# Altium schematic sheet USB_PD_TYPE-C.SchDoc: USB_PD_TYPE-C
size A4; Date: Not used; ApprovedBy: Not used; CheckedBy: Not used; Author: Not used; CompanyName: STMicroelectronics; DrawnBy: Not used; Engineer: Not used; Organization: Not used; Address1: Not used; Address2: Not used; Address3: Not used; Address4: Not used; DocumentNumber: Not used; Revision: Not used; SheetNumber: 5; SheetTotal: 12
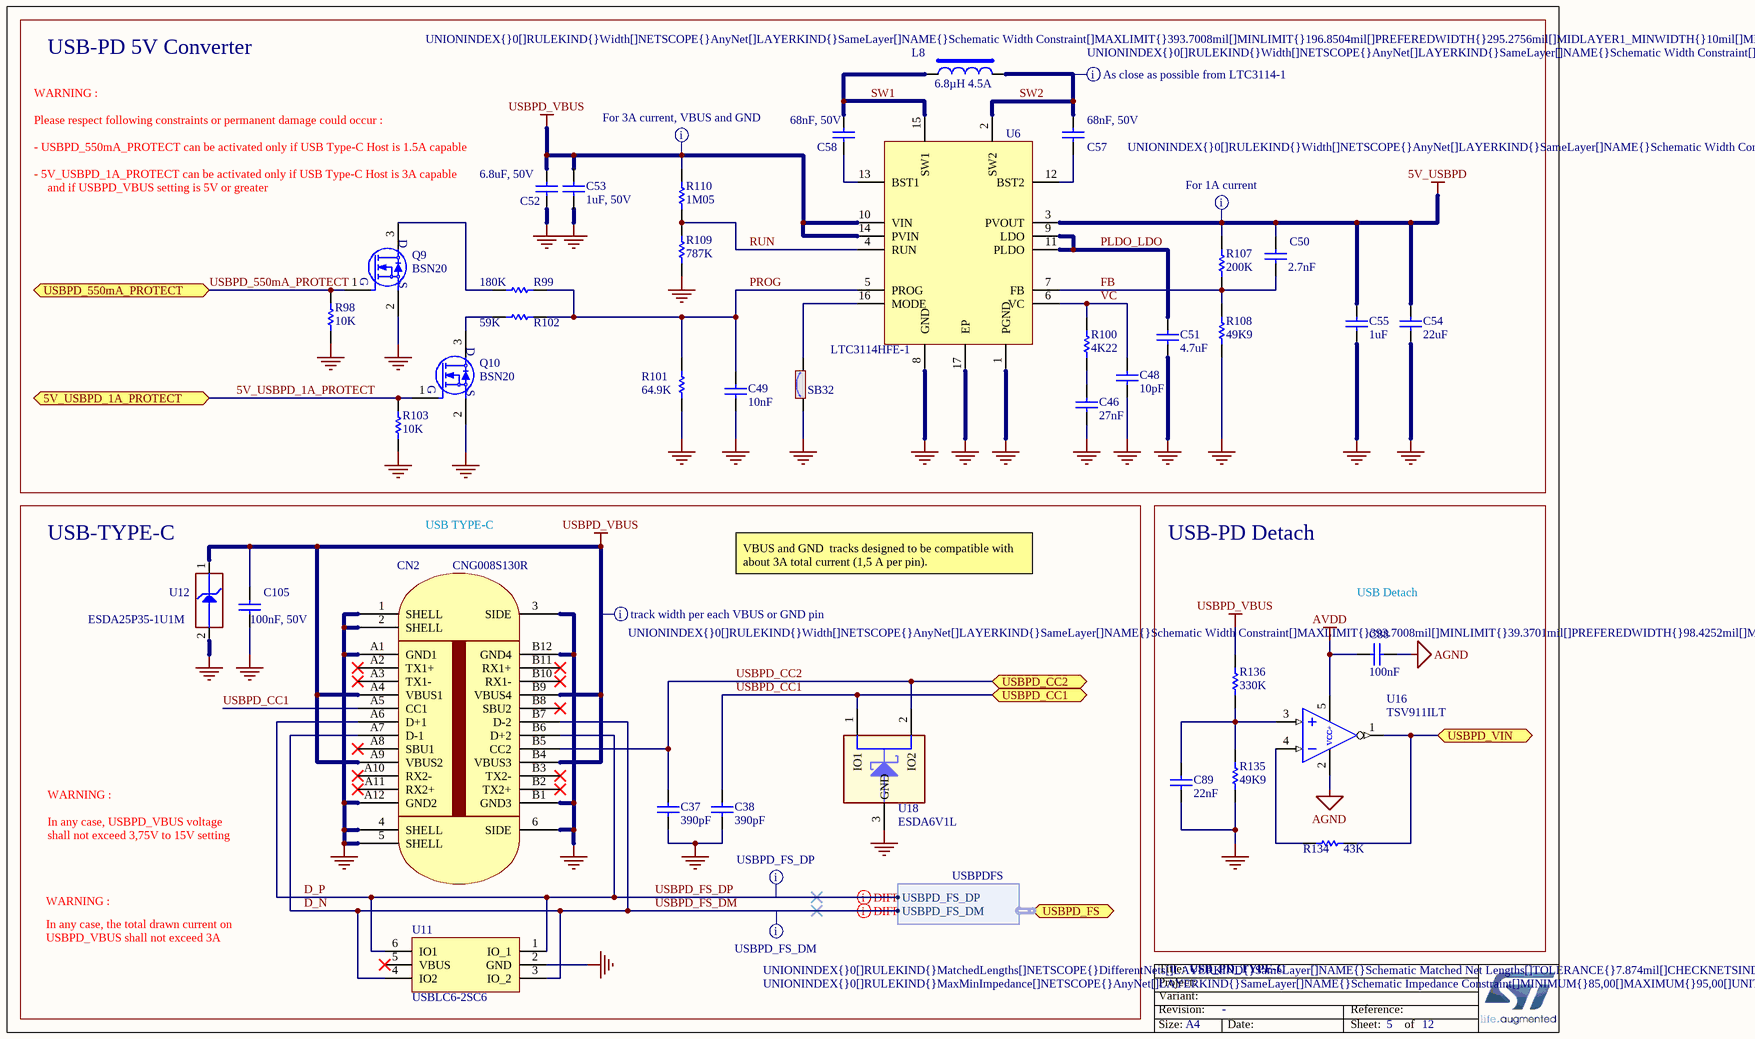
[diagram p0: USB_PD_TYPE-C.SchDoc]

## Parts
C37  value 390pF  [C0402]
C38  value 390pF  [C0402]
C46  value 27nF  [C0805_KEMET_IPC-7351_DENSITY-LEVEL-B_H1P10]  (hidden comment: Capacitor)
C48  value 10pF  [C0603]
C49  value 10nF  [C0603]
C50  value 2.7nF  [C0603_H0P8]  (hidden comment: Capacitor)
C51  value 4.7uF  [C0603]
C52  value 6.8uF, 50V  [C1206_H1P6]
C53  value 1uF, 50V  [C0603_H0P8]  (hidden comment: Capacitor)
C54  value 22uF  [C1210]
C55  value 1uF  [C0603]
C57  value 68nF, 50V  [C0603_H0P8]
C58  value 68nF, 50V  [C0603_H0P8]
C88  value 100nF  [C0402]
C89  value 22nF  [C1206_H0P85]
C105  value 100nF, 50V  [C0603]  (hidden comment: Capacitor)
CN2  value CNG008S130R  [CON_USB-TYPEC_LITKCONN-TECHNOLOGY_CNG008S130R]
L8  value 6.8µH 4.5A  [IND_8040_WURTH_74437358068]
Q9  value BSN20  [MOS_SOT23]
Q10  value BSN20  [MOS_SOT23]
R98  value 10K  [R0603]
R99  value 180K  [R0603]  (hidden comment: Resistor)
R100  value 4K22  [R0603_H0P45]
R101  value 64.9K  [R0603_H0P45]  (hidden comment: Resistor)
R102  value 59K  [R0603_H0P45]  (hidden comment: Resistor)
R103  value 10K  [R0603]
R107  value 200K  [R0603]  (hidden comment: Resistor)
R108  value 49K9  [R0603]  (hidden comment: Resistor)
R109  value 787K  [R0603_H0P45]
R110  value 1M05  [R0603_H0P45]
R134  value 43K  [R0603]
R135  value 49K9  [R0603]
R136  value 330K  [R0603]
SB32  (no value)  [SOLDER-BRIDGE_R0603-0R]
U6  value LTC3114HFE-1  [ICC_TSOP65P640X110_HS-17N]
U11  value USBLC6-2SC6  [ESD_SOT23-6L]
U12  value ESDA25P35-1U1M  [ESD_QFN1610_2N_1K_2A]
U16  value TSV911ILT  [AOP_SOT23-5L_H1P45]
U18  value ESDA6V1L  [ESD_SOT23]

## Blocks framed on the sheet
USB-PD 5V Converter: C46 C48-C55 C57 C58 L8 Q9 Q10 R98-R103 R107-R110 SB32 U6
USB-TYPE-C: C37 C38 C105 CN2 U11 U12 U18
USB-PD Detach: C88 C89 R134-R136 U16

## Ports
5V_USBPD_1A_PROTECT, USBPD_550mA_PROTECT, USBPD_CC1, USBPD_CC2, USBPD_FS (harness USBPDFS), USBPD_VIN

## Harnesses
USBPDFS: USBPD_FS_DM, USBPD_FS_DP

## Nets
5V_USBPD: C50.2 C54.2 C55.2 R107.2 U6.3(PVOUT)
AGND: C88.1 U16.2(VCC-)
AVDD: C88.2 U16.5(VCC+)
GND: C37.1 C38.1 C46.1 C48.1 C49.1 C51.2 C52.1 C53.1 C54.1 C55.1 C89.1 C105.1 CN2.1(SHELL) CN2.2(SHELL) CN2.3(SIDE) CN2.4(SHELL) CN2.5(SHELL) CN2.6(SIDE) CN2.A1(GND1) CN2.A12(GND2) CN2.B1(GND3) CN2.B12(GND4) Q9.2(S) Q10.2(S) R98.1 R101.1 R103.1 R108.1 R109.1 R135.1 SB32.1 U6.1(PGND) U6.8(GND) U6.17(EP) U11.2(GND) U12.2(GND) U18.3(GND)
USBPD_VBUS: C52.2 C53.2 C105.2 CN2.A4(VBUS1) CN2.A9(VBUS2) CN2.B4(VBUS3) CN2.B9(VBUS4) R110.2 R136.2 U6.10(VIN) U6.14(PVIN) U12.1(IO1)
5V_USBPD_1A_PROTECT: Q10.1(G) R103.2 ; port 5V_USBPD_1A_PROTECT
D_N: CN2.A7(D-1) CN2.B7(D-2) U11.3(IO_2) U11.4(IO2) ; port USBPD_FS.USBPD_FS_DM  [also labelled USBPD_FS_DM]
D_P: CN2.A6(D+1) CN2.B6(D+2) U11.1(IO_1) U11.6(IO1) ; port USBPD_FS.USBPD_FS_DP  [also labelled USBPD_FS_DP]
FB: C50.1 R107.1 R108.2 U6.7(FB)
PLDO_LDO: C51.1 U6.9(LDO) U6.11(PLDO)
PROG: C49.2 R99.2 R101.2 R102.2 U6.5(PROG)
RUN: R109.2 R110.1 U6.4(RUN)
SW1: C58.2 L8.1 U6.15(SW1)
SW2: C57.2 L8.2 U6.2(SW2)
USBPD_550mA_PROTECT: Q9.1(G) R98.2 ; port USBPD_550mA_PROTECT
USBPD_CC1: C38.2 CN2.A5(CC1) U18.1(IO1) ; port USBPD_CC1
USBPD_CC2: C37.2 CN2.B5(CC2) U18.2(IO2) ; port USBPD_CC2
USBPD_VIN: R134.2 U16.1(NC) ; port USBPD_VIN
VC: C48.2 R100.2 U6.6(VC)
NetC46_2: C46.2 R100.1
NetC57_1: C57.1 U6.12(BST2)
NetC58_1: C58.1 U6.13(BST1)
NetC89_2: C89.2 R135.2 R136.1 U16.3(IN+)
NetQ9_3: Q9.3(D) R99.1
NetQ10_3: Q10.3(D) R102.1
NetR134_1: R134.1 U16.4(IN-)
NetSB32_2: SB32.2 U6.16(MODE)

Not connected (* = marked no-connect by the designer): CN2 A2(TX1+)* A3(TX1-)* A8(SBU1)* A10(RX2-)* A11(RX2+)* B2(TX2+)* B3(TX2-)* B8(SBU2)* B10(RX1-)* B11(RX1+)*; U11 5(VBUS)*

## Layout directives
differential pair; rule Impedance Constraint [Min = 85.00    Max = 95.00    ]: D_N, D_P
rule Undefined; rule Matched Net Lengths [Tolerance = 0.2mm]; rule Impedance Constraint [Min = 85.00    Max = 95.00    ]: D_N, D_P
rule Width Constraint [Pref Width = 2.5mm    Min Width = 1mm    Max Width = 10mm]: USBPD_VBUS
rule Width Constraint [Pref Width = 5mm    Min Width = 5mm    Max Width = 10mm]: 5V_USBPD, SW2
rule Width Constraint [Pref Width = 7.5mm    Min Width = 5mm    Max Width = 10mm]: USBPD_VBUS

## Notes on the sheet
- WARNING :
- - USBPD_550mA_PROTECT can be activated only if USB Type-C Host is 1.5A capable
- - 5V_USBPD_1A_PROTECT can be activated only if USB Type-C Host is 3A capable
- Please respect following constraints or permanent damage could occur :
- and if USBPD_VBUS setting is 5V or greater
- USB TYPE-C
- VBUS and GND  tracks designed to be compatible with about 3A total current (1,5 A per pin).
- USB Detach
- shall not exceed 3,75V to 15V setting
- In any case, USBPD_VBUS voltage
- In any case, the total drawn current on
- USBPD_VBUS shall not exceed 3A

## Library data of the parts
C37 C38 = MCD-01597: Capacitor, MLCC, 390pF, 50V, NPO, 5%, 0402, T=0,5mm; Manufacturer_Part_Number: CC0402JRNPO9BN391; Manufacturer: YAGEO; Provided_By: SUBCO
C46 = MCD-01719: Capacitor, MLCC, 27nF, 25V, C0G, 5%, 0805, T=1.1mm; Manufacturer_Part_Number: C0805C273J3GACTU; Manufacturer: KEMET
C48 = MCD-00637: Capacitor, MLCC, 10pF, 50V, NPO, 5%, 0603, T=0,8mm; Manufacturer_Part_Number: CC0603JRNPO9BN100; Manufacturer: YAGEO; Provided_By: SUBCO
C49 = MCD-01007: Capacitor, MLCC, 10nF, 16V, X7R, 10%, 0603, T=0.8mm; Manufacturer_Part_Number: CC0603KRX7R7BB103; Manufacturer: YAGEO; Provided_By: SUBCO
C50 = MCD-01923: Capacitor, MLCC, 2.7nF, 16V, NPO, 5%, 0603, T=0,8mm; Manufacturer_Part_Number: CC0603JRNPO7BN272; Manufacturer: YAGEO; Provided_By: SUBCO
C51 = MCD-00009: Capacitor, MLCC, 4.7uF, 16V, X5R, 10%, 0603, T=0.8mm; Manufacturer_Part_Number: CC0603KRX5R7BB475; Manufacturer: YAGEO; Provided_By: SUBCO
C52 = MCD-01559: Capacitor, MLCC, 6.8uF, 50V, X5R, 10%, 1206, T=1.6mm; Manufacturer_Part_Number: C3216X5R1H685K160AB; Manufacturer: TDK; Provided_By: SUBCO
C53 = MCD-01703: Capacitor,1uF,50V,X5R,10%,0603, T=0.8mm; Manufacturer_Part_Number: CC0603KRX5R9BB105; Manufacturer: YAGEO; Provided_By: SUBCO
C54 = MCD-00614: Capacitor, MLCC, 22uF, 16V, 1210, X7R, 20%, T=2,5mm, ESR 2mohm@410KHz; Manufacturer_Part_Number: GCM32ER71C226ME19; Manufacturer: MURATA; Provided_By: SUBCO
C55 = MCD-00010: Capacitor, MLCC, 1uF, 16V, X5R, 10%, 0603, T=0,8mm; Manufacturer_Part_Number: CC0603KRX5R7BB105; Manufacturer: YAGEO; Provided_By: SUBCO
C57 C58 = MCD-01667: Capacitor, MLCC, 68nF, 50V, X7R, 10%, 0603, T=0.8mm; Manufacturer_Part_Number: CC0603KRX7R9BB683; Manufacturer: YAGEO; Provided_By: SUBCO
C88 = MCD-00102: Capacitor, MLCC, 100nF, 16V, X7R, 10%, 0402, T=0,5mm; Manufacturer_Part_Number: CC0402KRX7R7BB104; Manufacturer: YAGEO; Alternate_Manufacturer_Part_Number: GCM155R71C104KA55D; Alternate_Manufacturer: MURATA; Provided_By: SUBCO
C89 = MCD-01184: Capacitor, COG, 22nF,50V, X7S, 5%, 1206, T=0.85mm; Manufacturer_Part_Number: GRM3195C1H223JA01L; Manufacturer: MURATA; Provided_By: SUBCO
C105 = MCD-01099: Capacitor,100nF,50V,X7R,10%,0603; Manufacturer_Part_Number: CC0603KRX7R9BB104; Manufacturer: YAGEO; Provided_By: SUBCO
CN2 = MCD-01679: USB Type C certified Connector SMT Mid-mount; Manufacturer: LITKCON TECHNOLOGY; Provided_By: SUBCO
L8 = MCD-01372: Inductor 6.8µH +/-20% Isat= 13.5A DCR=33.40 mOhm; Manufacturer_Part_Number: 744 373 580 68; Manufacturer: WURTH; Provided_By: SUBCO
Q9 Q10 = MCD-00151: N-channel enhancement mode field-effect transistor; Part_Type: IC; Manufacturer: NXP; Provided_By: SUBCO
R98 R103 = MCD-00220: Resistor,10K,0603,1%,1/10W; Manufacturer_Part_Number: RC0603FR-0710KL; Manufacturer: YAGEO; Provided_By: SUBCO
R99 = MCD-00414: Resistor,180K,0603,1%,1/10W; Manufacturer_Part_Number: RC0603FR-07180KL; Manufacturer: YAGEO; ECCN_US: EAR99; ECCN_EU: NEC; Provided_By: SUBCO
R100 = MCD-01571: Resistor, 4K22, 0603, 1%, 1/10W; Manufacturer_Part_Number: RC0603FR-074K22L; Manufacturer: YAGEO; Provided_By: SUBCO
R101 = MCD-01793: Resistor, 64.9K, 0603, 1%, 1/10W; Manufacturer_Part_Number: RC0603FR-0764K9L; Manufacturer: YAGEO; ECCN_US: EAR99; ECCN_EU: NEC; Provided_By: SUBCO
R102 = MCD-01794: Resistor, 59K, 0603, 1%, 1/10W; Manufacturer_Part_Number: RC0603FR-0759KL; Manufacturer: YAGEO; ECCN_US: EAR99; ECCN_EU: NEC; Provided_By: SUBCO
R107 = MCD-00424: Resistor,200K,0603,1%,1/10W; Manufacturer_Part_Number: RC0603FR-07200KL; Manufacturer: YAGEO; ECCN_US: EAR99; ECCN_EU: NEC; Provided_By: SUBCO
R108 = MCD-01171: Resistor,49K9,0603,1%; Manufacturer_Part_Number: RC0603FR-0749K9L; Manufacturer: YAGEO; ECCN_US: EAR99; ECCN_EU: NEC; Provided_By: SUBCO
R109 = MCD-01568: Resistor, 787K, 0603, 1%, 1/10W; Manufacturer_Part_Number: RC0603FR-07787KL; Manufacturer: YAGEO; Provided_By: SUBCO
R110 = MCD-01569: Resistor, 1M05, 0603, 1%, 1/10W; Manufacturer_Part_Number: RC0603FR-071M05L; Manufacturer: YAGEO; Provided_By: SUBCO
R134 = MCD-00478: Resistor,43K,0603,1%,1/10W; Manufacturer_Part_Number: RC0603FR-0743KL; Manufacturer: YAGEO; Provided_By: SUBCO
R135 = MCD-01171: Resistor,49K9,0603,1%; Manufacturer_Part_Number: RC0603FR-0749K9L; Manufacturer: YAGEO; Provided_By: SUBCO
R136 = MCD-00458: Resistor,330K,0603,1%,1/10W; Manufacturer_Part_Number: RC0603FR-07330KL; Manufacturer: YAGEO; Provided_By: SUBCO
SB32 = MCD-00071: Solder Bridge ON; Part_Type: Mechanical; Manufacturer_Part_Number: RC0603JR-070RL; Manufacturer: YAGEO; Provided_By: SUBCO
U6 = MCD-01593: Integrated Circuit 40V, 1A Synchronous Buck-Boost DC/DC Converter with Programmable Output Current, -40°C to 150°C; Part_Type: IC; Manufacturer_Part_Number: LTC3114HFE-1-TRPBF; Manufacturer: LINEAR TECHNOLOGY; Provided_By: SUBCO
U11 = MCD-00163: Very low capacitance ESD protection; Part_Type: IC; Manufacturer: STMICROELECTRONICS; BMS_Part_Number: 9151075; Provided_By: SUBCO with ST control
U12 = MCD-01207: High power Transient voltage suppressor:25V/35A EOS and ESD transients protection.; Part_Type: Diode; Manufacturer: STMICROELECTRONICS; BMS_Part_Number: 9179045; Provided_By: SUBCO with ST control
U16 = MCD-01192: Single, dual, and quad rail to rail input/ouput 8Mhz operational amplifiers; Part_Type: IC; Manufacturer: STMICROELECTRONICS; BMS_Part_Number: 9177436; Provided_By: SUBCO with ST control
U18 = MCD-00255: Dual Transil array ESD protection; Part_Type: Diode; Manufacturer: STMICROELECTRONICS; BMS_Part_Number: 9179033; Provided_By: SUBCO with ST control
